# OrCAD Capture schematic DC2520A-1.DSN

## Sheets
1 PAGE1: size Custom; rev: 1
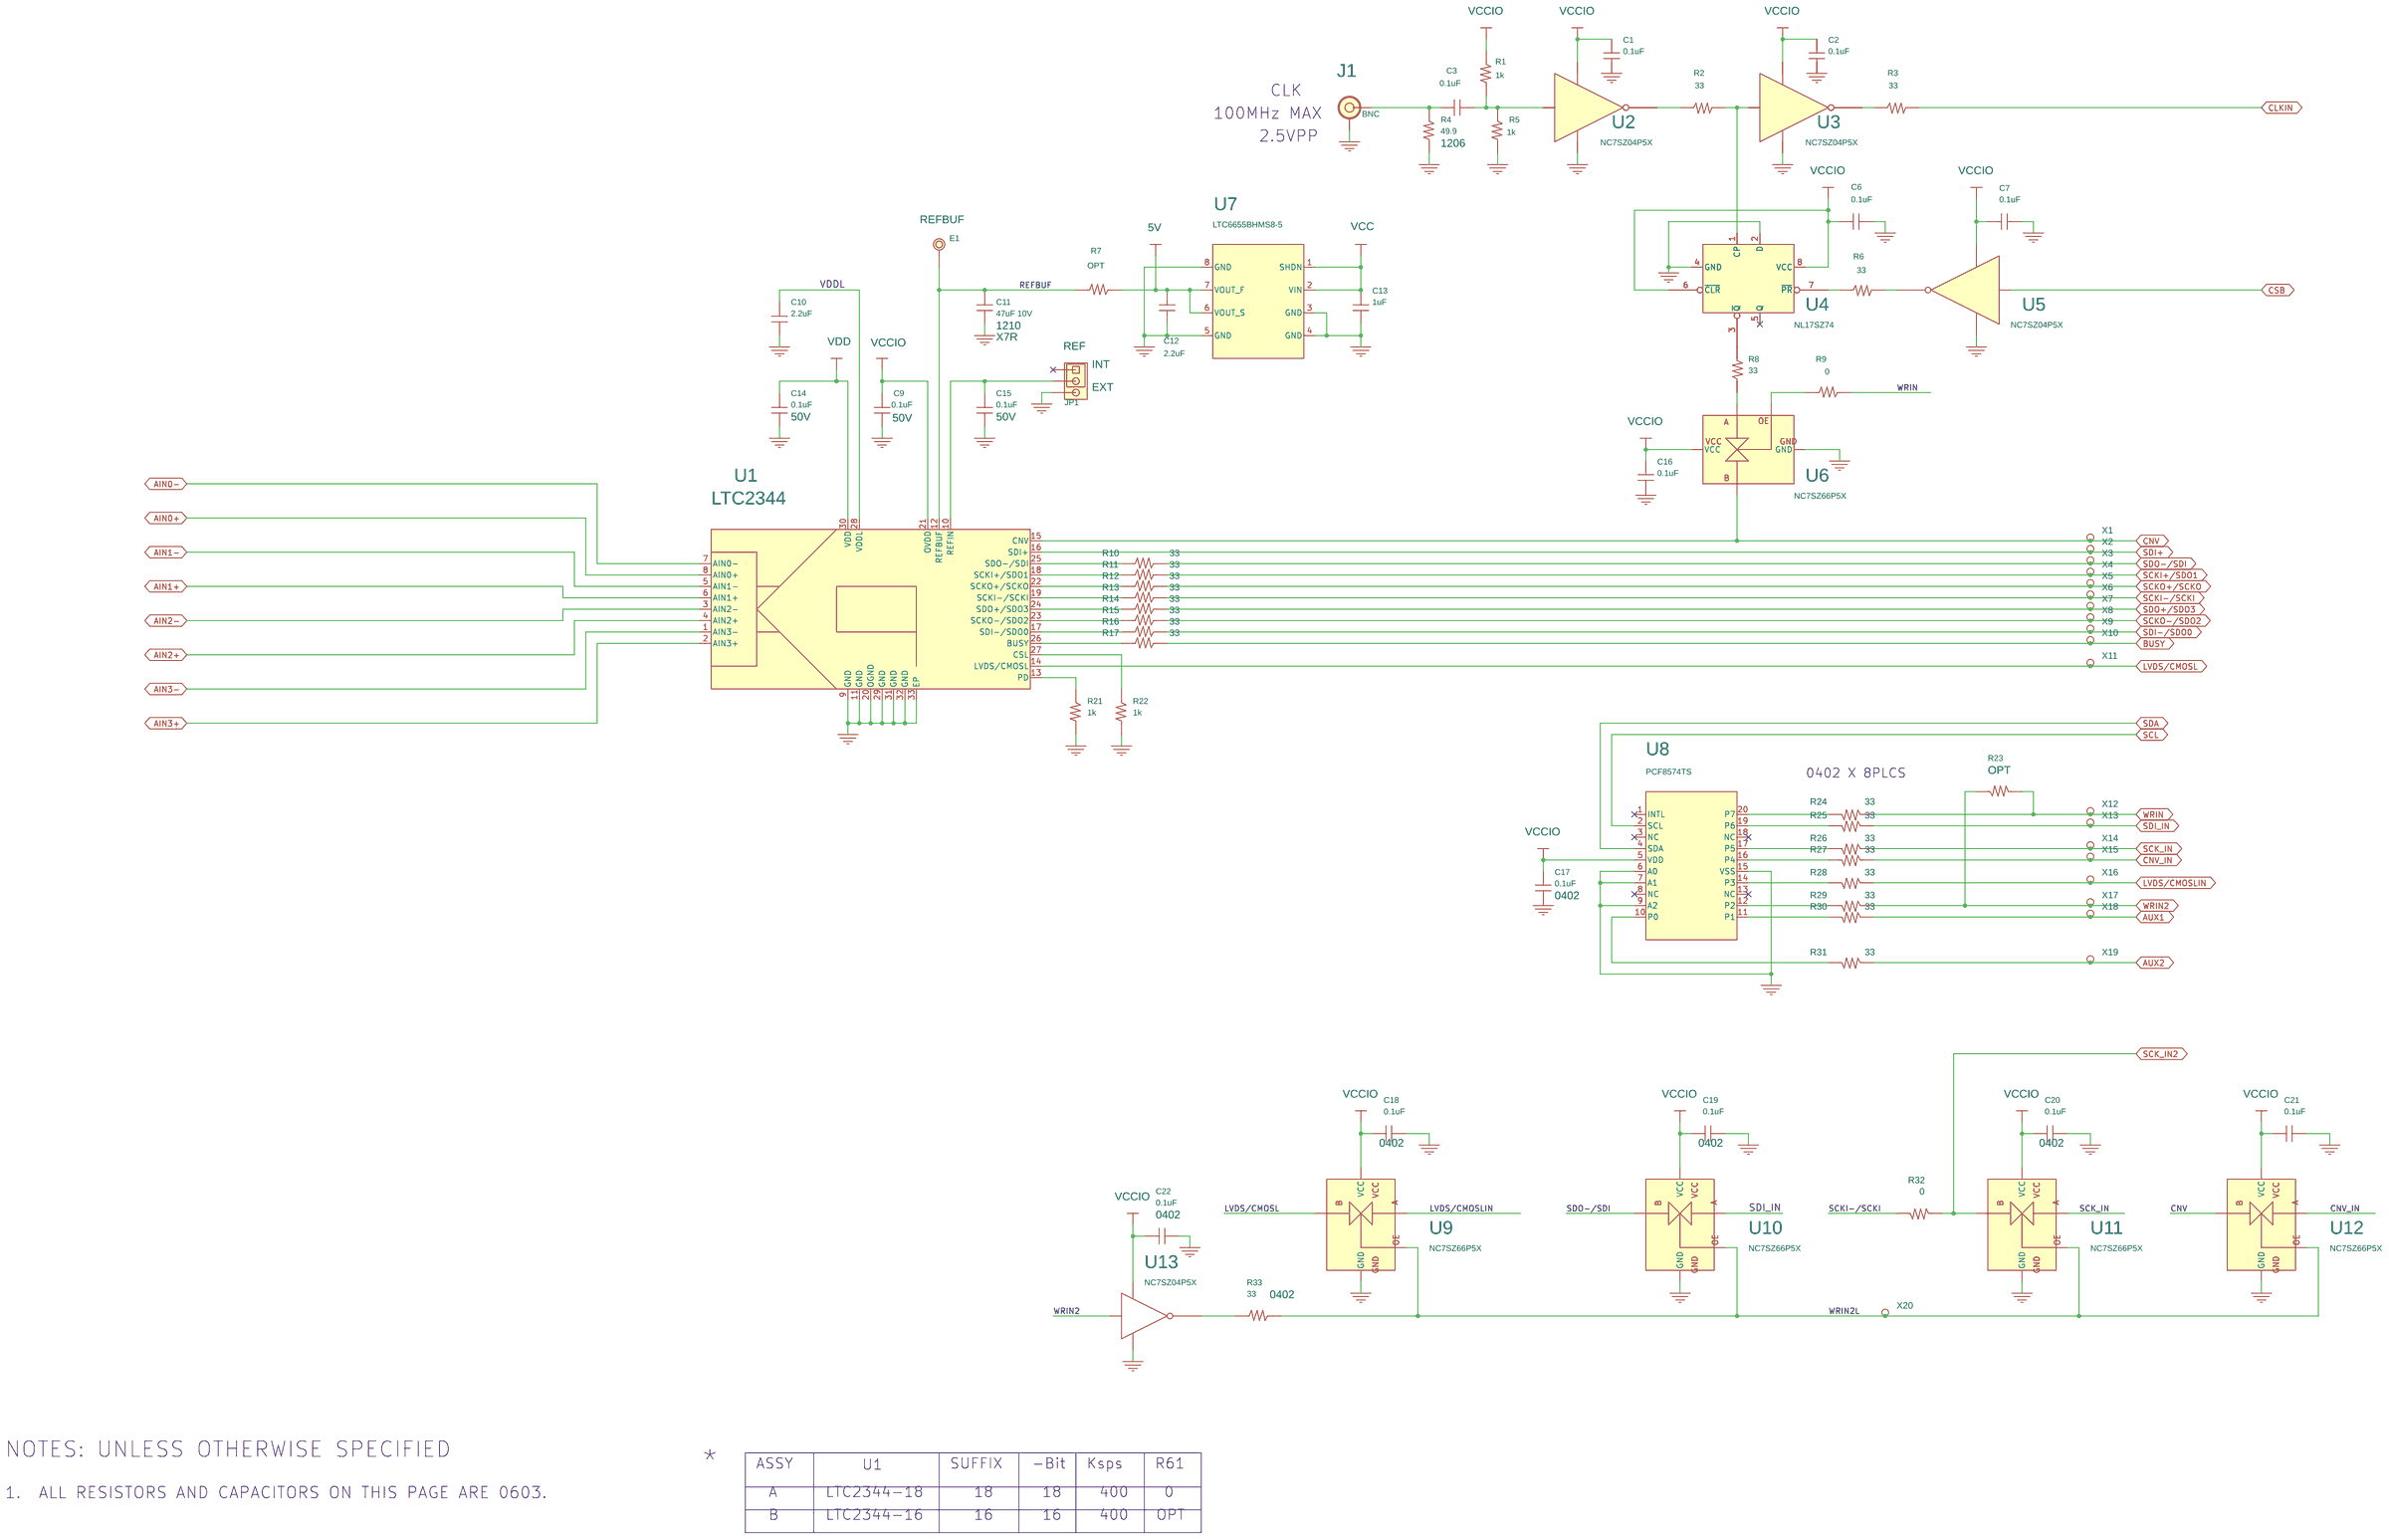
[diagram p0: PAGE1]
2 PAGE2: size B; title: 4-CHANNEL, SOFTSPAN, HIGH SPEED, SERIAL, SAR, ADC; company: LTC2344IUH-18/16; note: DEMO CIRCUIT 2520A; note: B
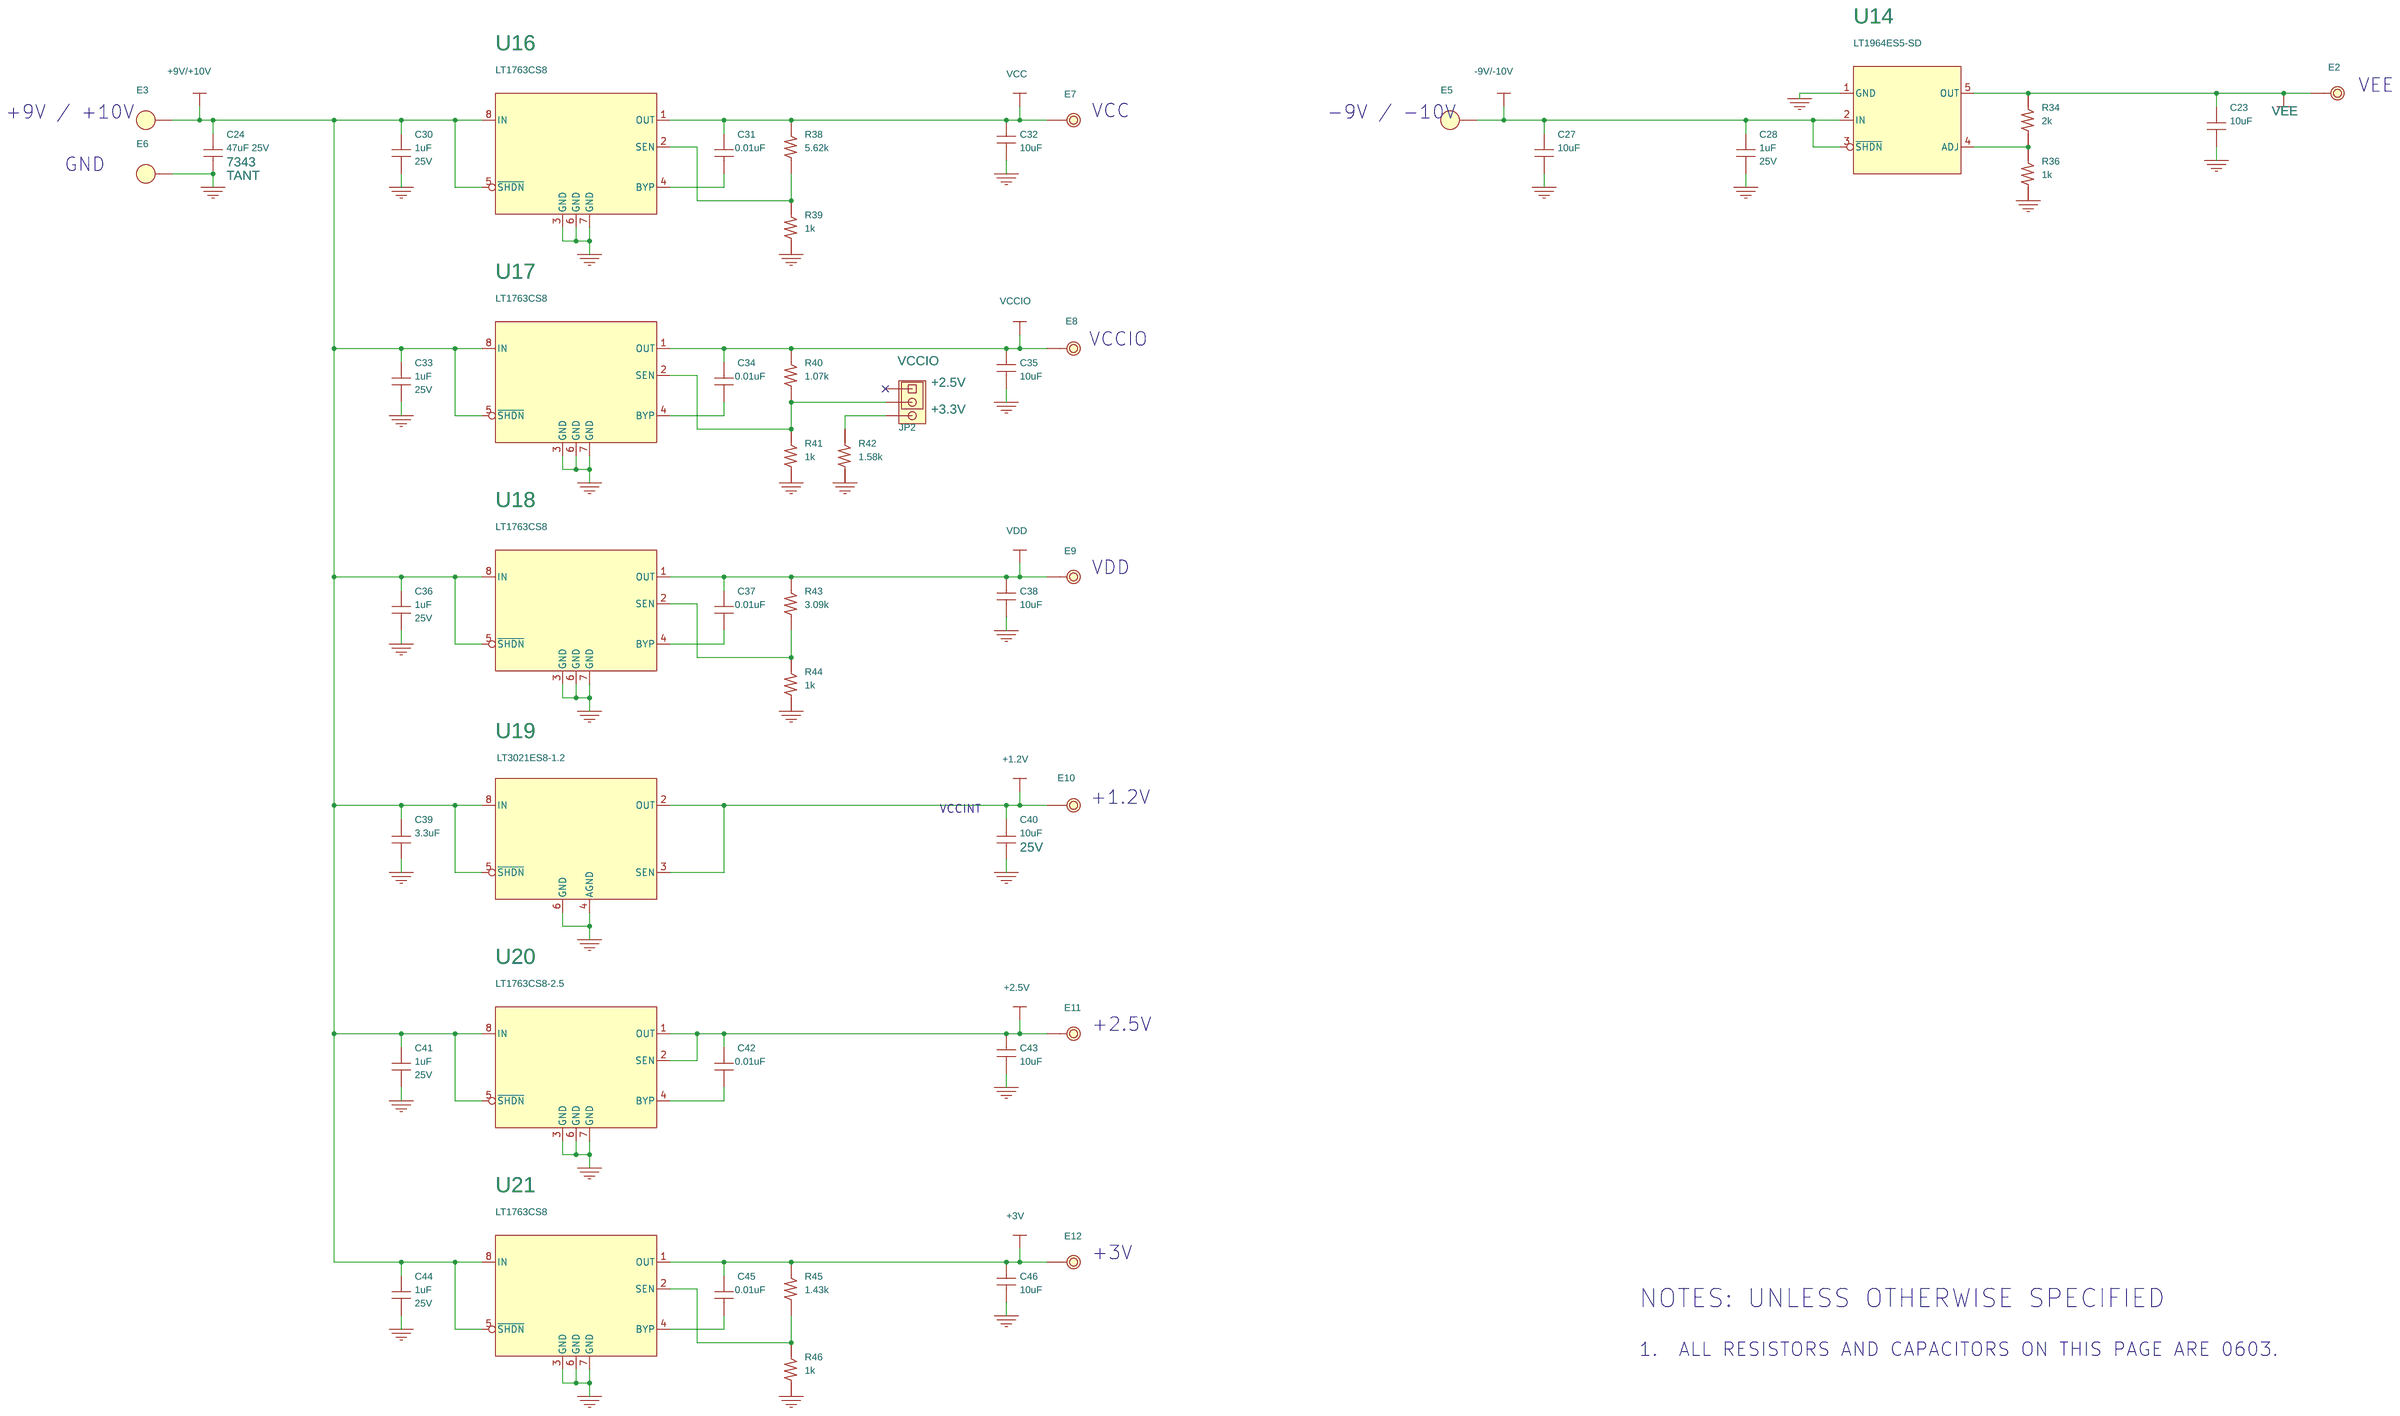
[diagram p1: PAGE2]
3 PAGE3: size B; title: 4-CHANNEL, SOFTSPAN, HIGH SPEED, SERIAL, SAR, ADC; company: LTC2344IUH-18/16; note: DEMO CIRCUIT 2520A; note: B
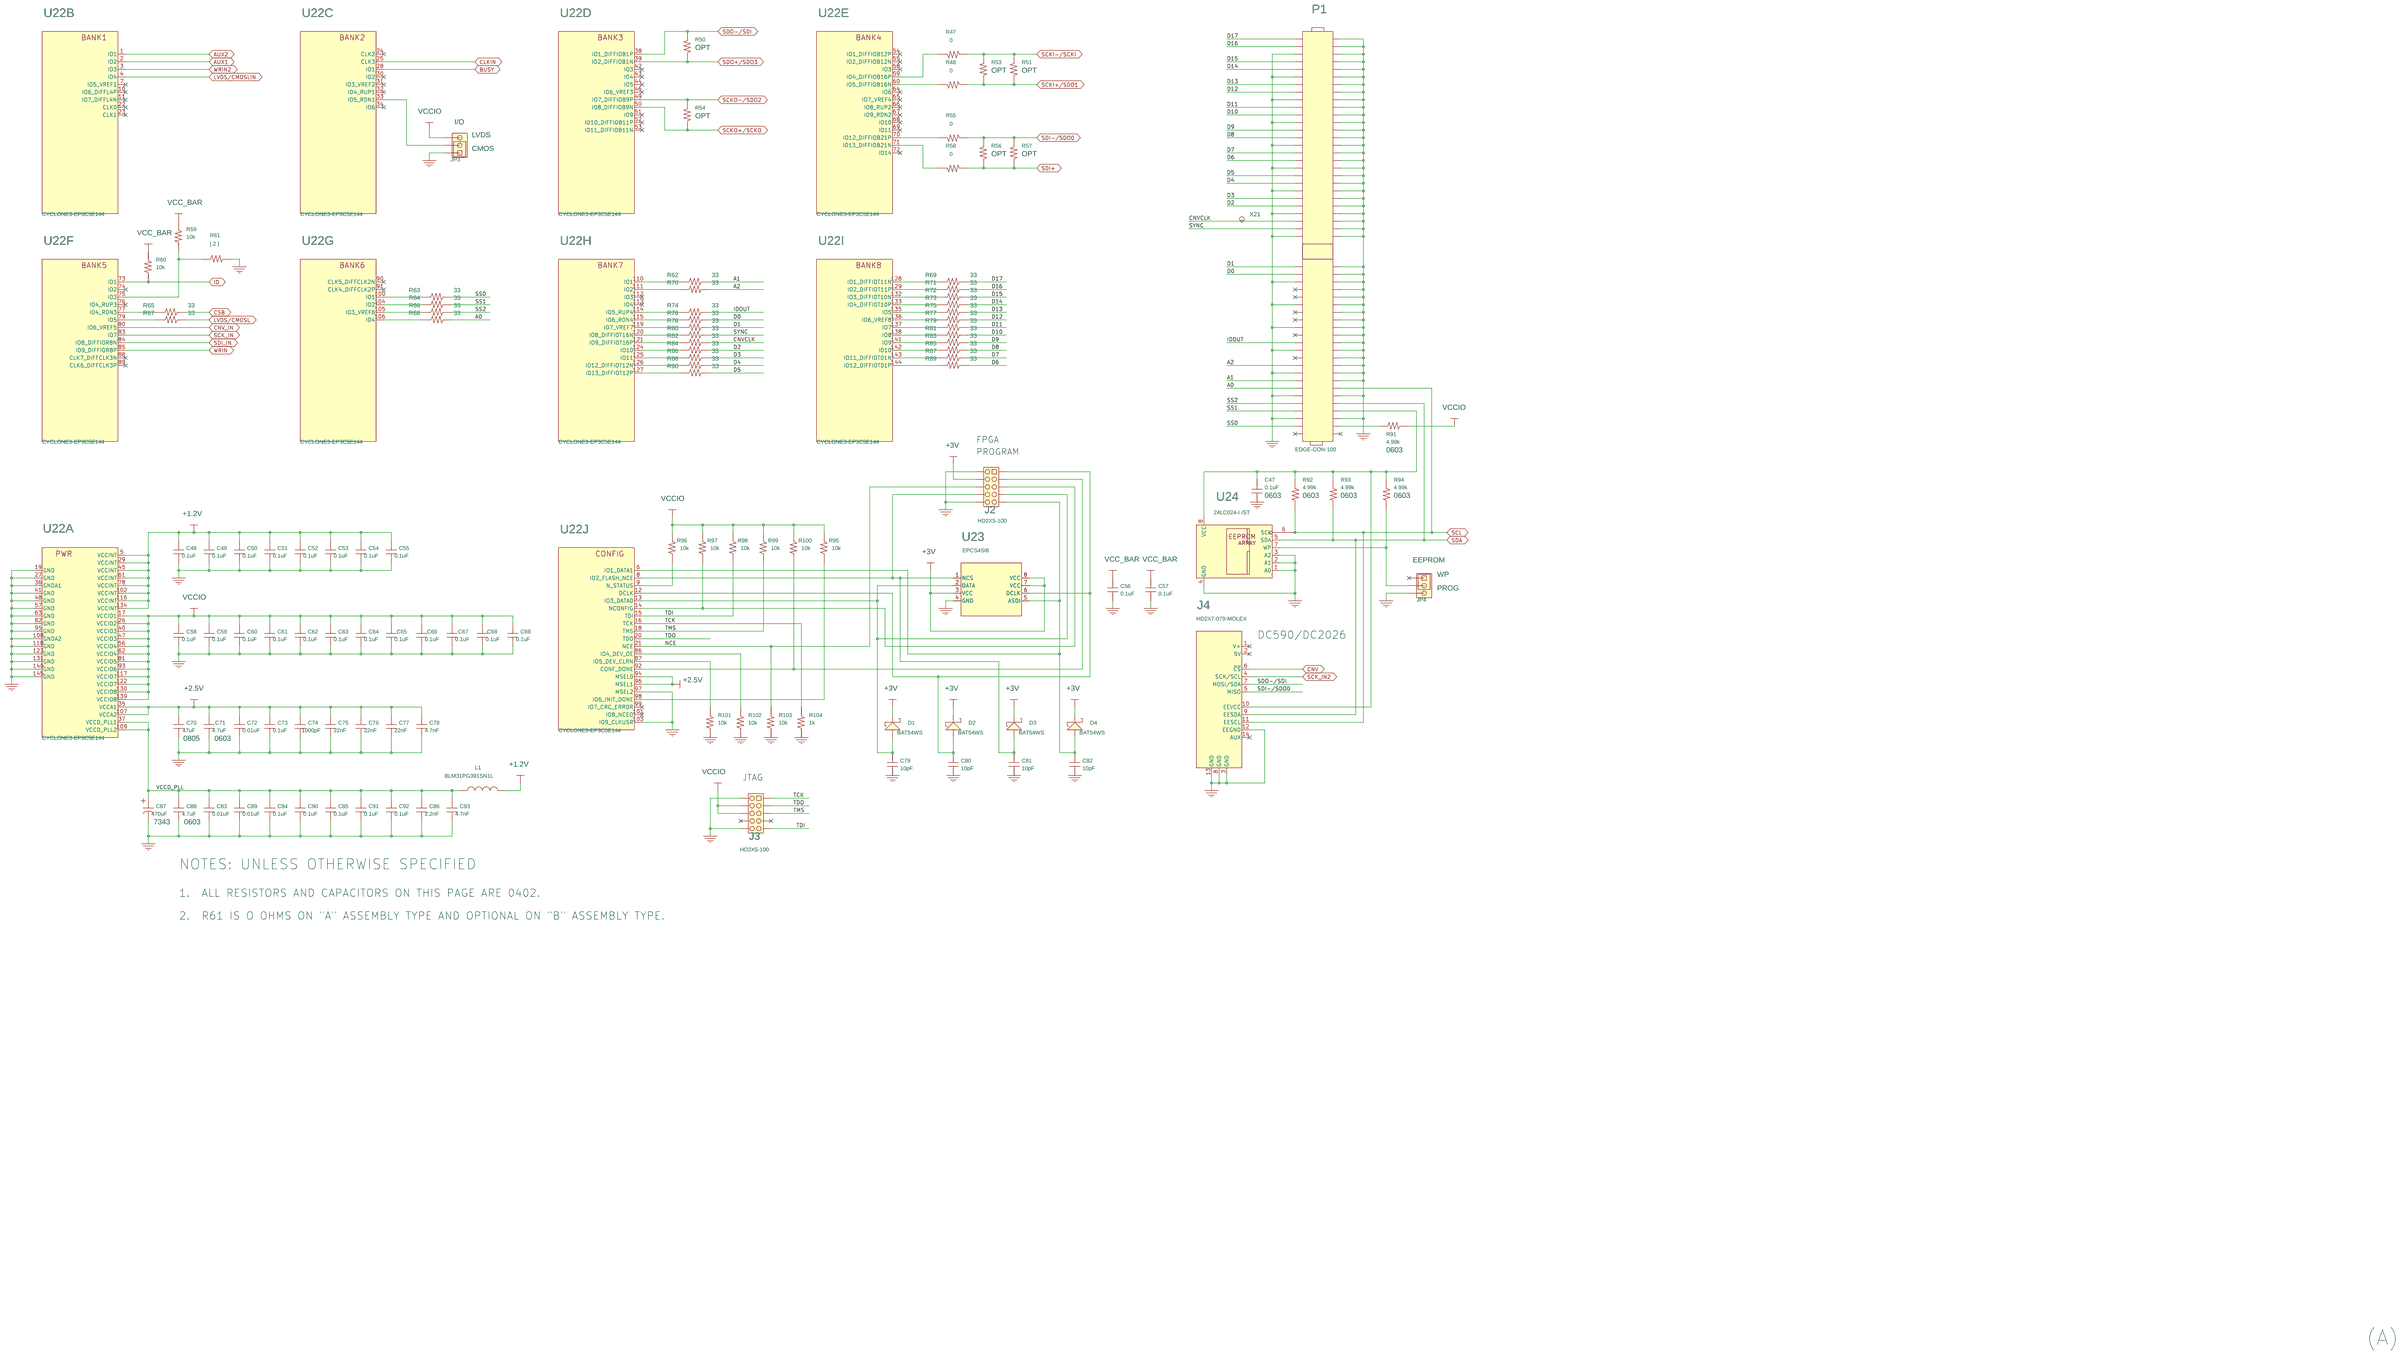
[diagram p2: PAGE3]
4 PAGE4: size C; title: 4-CHANNEL, SOFTSPAN, HIGH SPEED, SERIAL, SAR, ADC; company: LTC2344IUH-18/16; note: DEMO CIRCUIT 2520A; note: B
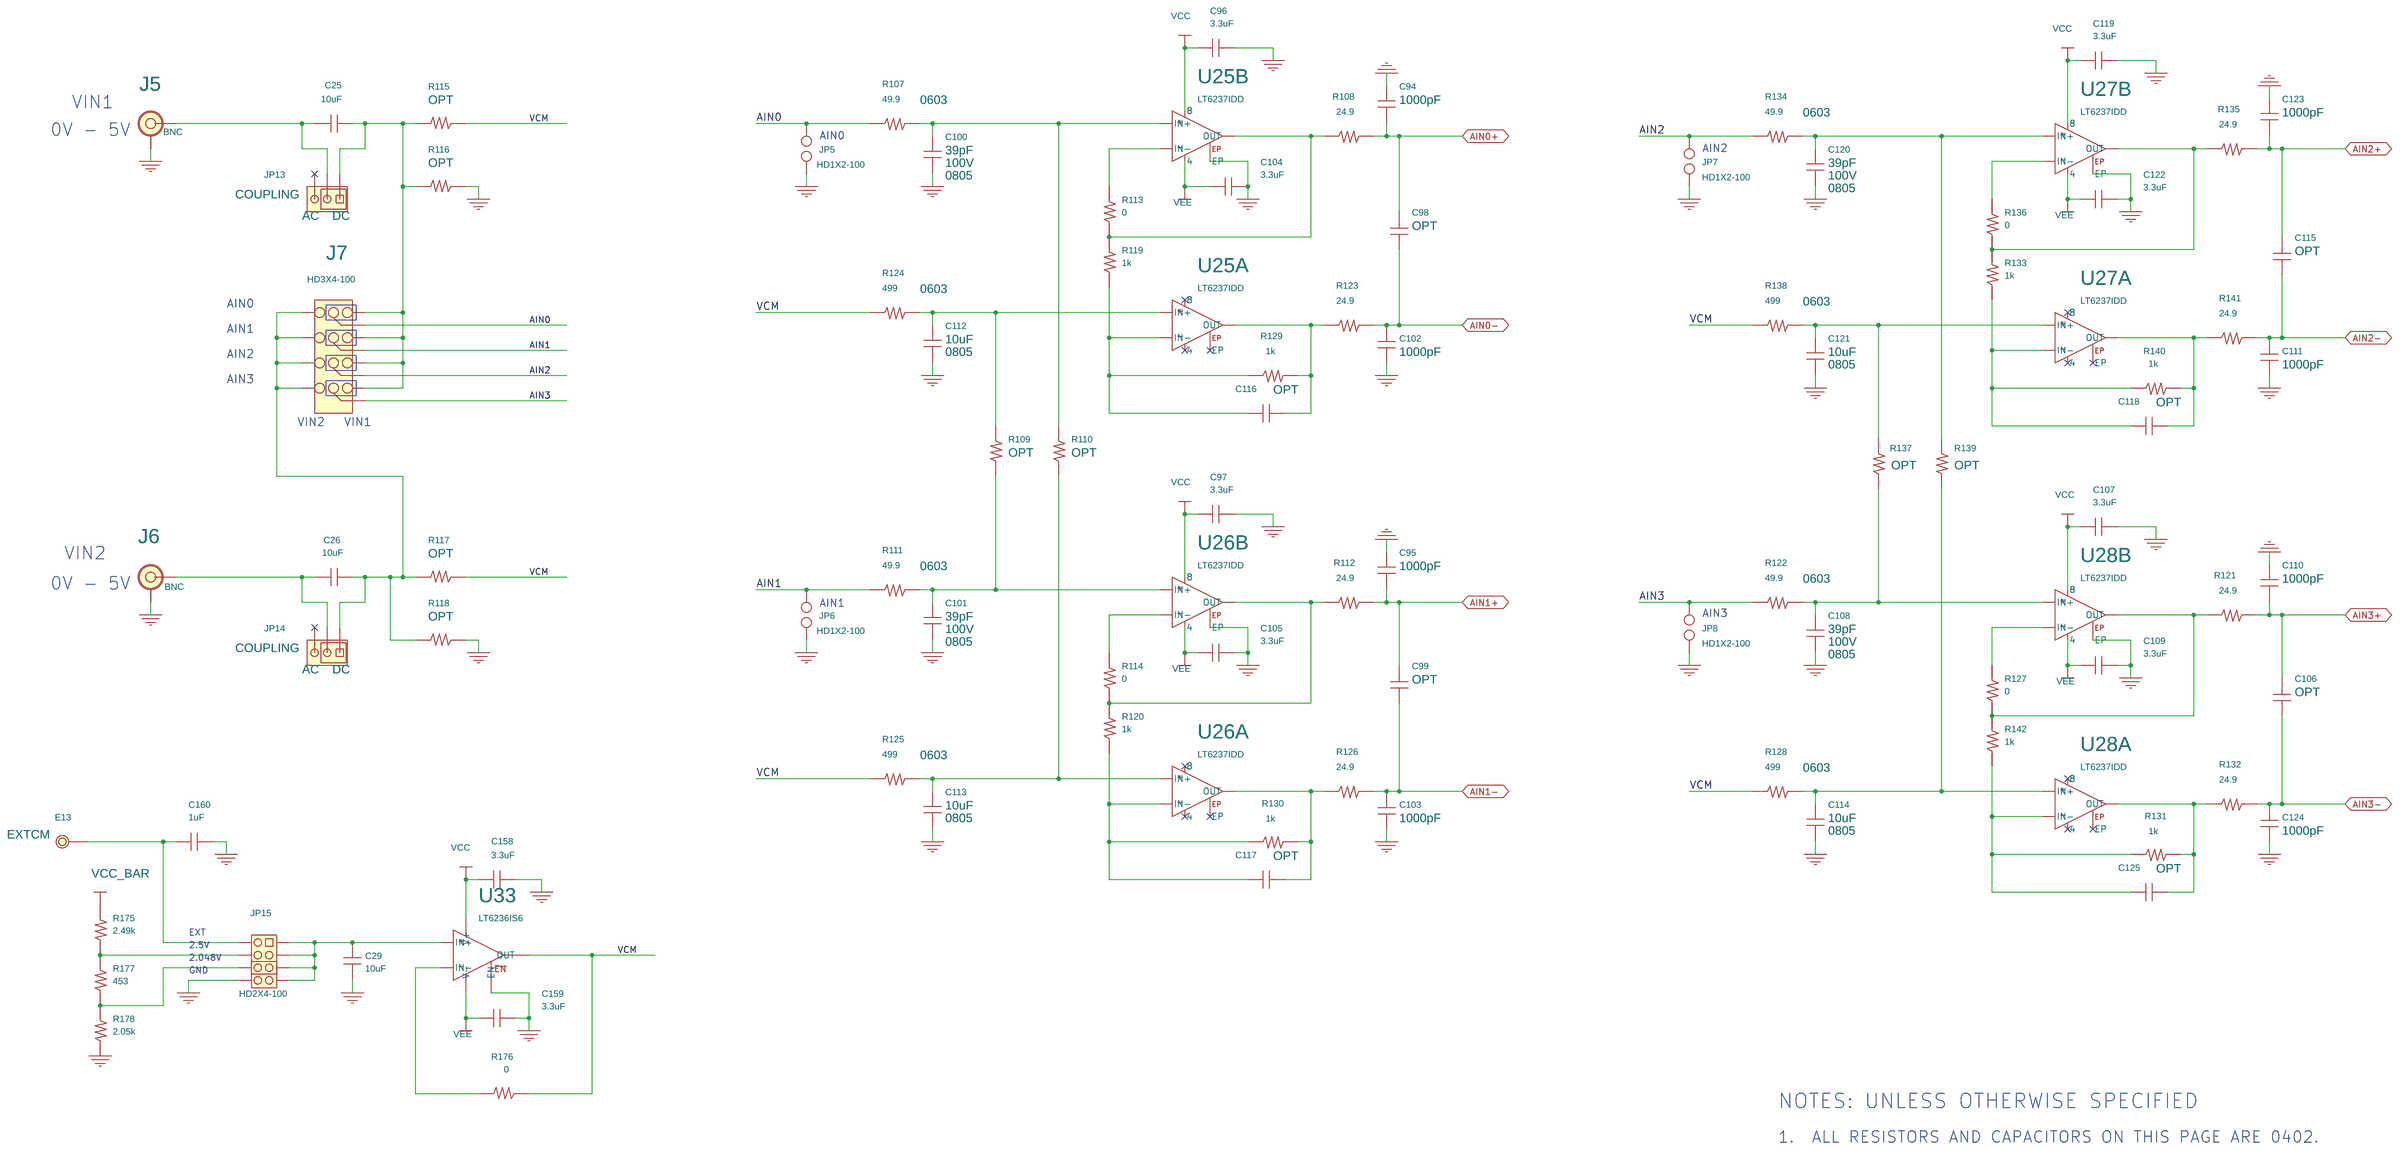
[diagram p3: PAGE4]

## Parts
sheet PAGE1
C1  0.1uF  [0603]
C2  0.1uF  [0603]
C3  0.1uF  [0603]
C6  0.1uF  [0603]
C7  0.1uF  [0603]
C9  0.1uF  [0603]
C10  2.2uF  [0603]
C11  47uF 10V  [1210]
C12  2.2uF  [0603]
C13  1uF  [0603]
C14  0.1uF  [0603]
C15  0.1uF  [0603]
C16  0.1uF  [0603]
C17  0.1uF  [0402]
C18  0.1uF  [0402]
C19  0.1uF  [0402]
C20  0.1uF  [0402]
C21  0.1uF  [0603]
C22  0.1uF  [0402]
E1  MILL-MAX-2308  [MILL-MAX-2308]
J1  BNC  [BNC5]
JP1  HD1X3-100  [HD1X3-100]
R1  1k  [0603]
R2  33  [0603]
R3  33  [0603]
R4  49.9  [1206]
R5  1k  [0603]
R6  33  [0603]
R7  OPT  [0603]
R8  33  [0603]
R9  0  [0603]
R10  33  [0603]
R11  33  [0603]
R12  33  [0603]
R13  33  [0603]
R14  33  [0603]
R15  33  [0603]
R16  33  [0603]
R17  33  [0603]
R21  1k  [0603]
R22  1k  [0603]
R23  R-0402  [0402]
R24  33  [0402]
R25  33  [0402]
R26  33  [0402]
R27  33  [0402]
R28  33  [0402]
R29  33  [0402]
R30  33  [0402]
R31  33  [0402]
R32  0  [0402]
R33  33  [0402]
U1  LTC2344  [QFN32UH-5X5]
U2  NC7SZ04P5X  [SC70-5]
U3  NC7SZ04P5X  [SC70-5]
U4  NL17SZ74  [US8]
U5  NC7SZ04P5X  [SC70-5]
U6  NC7SZ66P5X  [SC70-5]
U7  LTC6655BHMS8-5  [MSOP8]
U8  PCF8574TS  [SSOP20]
U9  NC7SZ66P5X  [SC70-5]
U10  NC7SZ66P5X  [SC70-5]
U11  NC7SZ66P5X  [SC70-5]
U12  NC7SZ66P5X  [SC70-5]
U13  NC7SZ04P5X  [SC70-5]
X1  PAD050-030  [PAD050-030]
X2  PAD050-030  [PAD050-030]
X3  PAD050-030  [PAD050-030]
X4  PAD050-030  [PAD050-030]
X5  PAD050-030  [PAD050-030]
X6  PAD050-030  [PAD050-030]
X7  PAD050-030  [PAD050-030]
X8  PAD050-030  [PAD050-030]
X9  PAD050-030  [PAD050-030]
X10  PAD050-030  [PAD050-030]
X11  PAD050-030  [PAD050-030]
X12  PAD050-030  [PAD050-030]
X13  PAD050-030  [PAD050-030]
X14  PAD050-030  [PAD050-030]
X15  PAD050-030  [PAD050-030]
X16  PAD050-030  [PAD050-030]
X17  PAD050-030  [PAD050-030]
X18  PAD050-030  [PAD050-030]
X19  PAD050-030  [PAD050-030]
X20  PAD050-030  [PAD050-030]
sheet PAGE2
C23  10uF  [0603]
C24  47uF 25V  [7343]
C27  10uF  [0603]
C28  1uF  [0603]
C30  1uF  [0603]
C31  0.01uF  [0603]
C32  10uF  [0603]
C33  1uF  [0603]
C34  0.01uF  [0603]
C35  10uF  [0603]
C36  1uF  [0603]
C37  0.01uF  [0603]
C38  10uF  [0603]
C39  3.3uF  [0603]
C40  10uF  [0603]
C41  1uF  [0603]
C42  0.01uF  [0603]
C43  10uF  [0603]
C44  1uF  [0603]
C45  0.01uF  [0603]
C46  10uF  [0603]
E2  MILL-MAX-2308  [MILL-MAX-2308]
E3  MILL-MAX-2501  [MILL-MAX-2501]
E5  MILL-MAX-2501  [MILL-MAX-2501]
E6  MILL-MAX-2501  [MILL-MAX-2501]
E7  MILL-MAX-2308  [MILL-MAX-2308]
E8  MILL-MAX-2308  [MILL-MAX-2308]
E9  MILL-MAX-2308  [MILL-MAX-2308]
E10  MILL-MAX-2308  [MILL-MAX-2308]
E11  MILL-MAX-2308  [MILL-MAX-2308]
E12  MILL-MAX-2308  [MILL-MAX-2308]
JP2  HD1X3-100  [HD1X3-100]
R34  2k  [0603]
R36  1k  [0603]
R38  5.62k  [0603]
R39  1k  [0603]
R40  1.07k  [0603]
R41  1k  [0603]
R42  1.58k  [0603]
R43  3.09k  [0603]
R44  1k  [0603]
R45  1.43k  [0603]
R46  1k  [0603]
U14  LT1964ES5-SD  [SOT23-S5]
U16  LT1763CS8  [SO8]
U17  LT1763CS8  [SO8]
U18  LT1763CS8  [SO8]
U19  LT3021ES8-1.2  [SO8]
U20  LT1763CS8-2.5  [SO8]
U21  LT1763CS8  [SO8]
sheet PAGE3
C47  0.1uF  [0603]
C48  0.1uF  [0402]
C49  0.1uF  [0402]
C50  0.1uF  [0402]
C51  0.1uF  [0402]
C52  0.1uF  [0402]
C53  0.1uF  [0402]
C54  0.1uF  [0402]
C55  0.1uF  [0402]
C56  0.1uF  [0402]
C57  0.1uF  [0402]
C58  0.1uF  [0402]
C59  0.1uF  [0402]
C60  0.1uF  [0402]
C61  0.1uF  [0402]
C62  0.1uF  [0402]
C63  0.1uF  [0402]
C64  0.1uF  [0402]
C65  0.1uF  [0402]
C66  0.1uF  [0402]
C67  0.1uF  [0402]
C68  0.1uF  [0402]
C69  0.1uF  [0402]
C70  47uF  [0805]
C71  4.7uF  [0603]
C72  0.01uF  [0402]
C73  0.1uF  [0402]
C74  1000pF  [0402]
C75  22nF  [0402]
C76  22nF  [0402]
C77  22nF  [0402]
C78  4.7nF  [0402]
C79  10pF  [0402]
C80  10pF  [0402]
C81  10pF  [0402]
C82  10pF  [0402]
C83  0.01uF  [0402]
C84  0.1uF  [0402]
C85  0.1uF  [0402]
C86  2.2nF  [0402]
C87  470uF  [7343]
C88  4.7uF  [0603]
C89  0.01uF  [0402]
C90  0.1uF  [0402]
C91  0.1uF  [0402]
C92  0.1uF  [0402]
C93  4.7nF  [0402]
D1  BAT54WS  [SOD323]
D2  BAT54WS  [SOD323]
D3  BAT54WS  [SOD323]
D4  BAT54WS  [SOD323]
J2  HD2X5-100  [HD2X5-100]
J3  HD2X5-100  [HD2X5-100]
J4  HD2X7-079-MOLEX  [HD2X7-079-MOLEX]
JP3  HD1X3-100  [HD1X3-100]
JP4  HD1X3-100  [HD1X3-100]
L1  BLM31PG391SN1L  [1206]
P1  EDGE-CON-100  [CON-GOLD-100P-TB]
R47  0  [0402]
R48  0  [0402]
R50  R-0402  [0402]
R51  R-0402  [0402]
R53  R-0402  [0402]
R54  R-0402  [0402]
R55  0  [0402]
R56  R-0402  [0402]
R57  R-0402  [0402]
R58  0  [0402]
R59  10k  [0402]
R60  10k  [0402]
R61  [ 2 ]  [0402]
R62  33  [0402]
R63  33  [0402]
R64  33  [0402]
R65  33  [0402]
R66  33  [0402]
R67  33  [0402]
R68  33  [0402]
R69  33  [0402]
R70  33  [0402]
R71  33  [0402]
R72  33  [0402]
R73  33  [0402]
R74  33  [0402]
R75  33  [0402]
R76  33  [0402]
R77  33  [0402]
R78  33  [0402]
R79  33  [0402]
R80  33  [0402]
R81  33  [0402]
R82  33  [0402]
R83  33  [0402]
R84  33  [0402]
R85  33  [0402]
R86  33  [0402]
R87  33  [0402]
R88  33  [0402]
R89  33  [0402]
R90  33  [0402]
R91  4.99k  [0603]
R92  4.99k  [0603]
R93  4.99k  [0603]
R94  4.99k  [0603]
R95  10k  [0402]
R96  10k  [0402]
R97  10k  [0402]
R98  10k  [0402]
R99  10k  [0402]
R100  10k  [0402]
R101  10k  [0402]
R102  10k  [0402]
R103  10k  [0402]
R104  1k  [0402]
U22  CYCLONE3-EP3C5E144  [EQFP144]  (sections A,B,C,D,E,F,G,H,I,J)
U23  EPCS4SI8  [SO8]
U24  24LC024-I /ST  [TSSOP8]
X21  PAD050-030  [PAD050-030]
sheet PAGE4
C25  10uF  [0603]
C26  10uF  [0603]
C29  10uF  [0603]
C94  1000pF  [0402]
C95  1000pF  [0402]
C96  3.3uF  [0402]
C97  3.3uF  [0402]
C98  C-0402  [0402]
C99  C-0402  [0402]
C100  39pF  [0805]
C101  39pF  [0805]
C102  1000pF  [0402]
C103  1000pF  [0402]
C104  3.3uF  [0402]
C105  3.3uF  [0402]
C106  C-0402  [0402]
C107  3.3uF  [0402]
C108  39pF  [0805]
C109  3.3uF  [0402]
C110  1000pF  [0402]
C111  1000pF  [0402]
C112  10uF  [0805]
C113  10uF  [0805]
C114  10uF  [0805]
C115  C-0402  [0402]
C116  C-0402  [0402]
C117  C-0402  [0402]
C118  C-0402  [0402]
C119  3.3uF  [0402]
C120  39pF  [0805]
C121  10uF  [0805]
C122  3.3uF  [0402]
C123  1000pF  [0402]
C124  1000pF  [0402]
C125  C-0402  [0402]
C158  3.3uF  [0402]
C159  3.3uF  [0402]
C160  1uF  [0402]
E13  MILL-MAX-2308  [MILL-MAX-2308]
J5  BNC  [BNC5]
J6  BNC  [BNC5]
J7  HD3X4-100  [HD3X4-100]
JP5  HD1X2-100  [HD1X2-100]
JP6  HD1X2-100  [HD1X2-100]
JP7  HD1X2-100  [HD1X2-100]
JP8  HD1X2-100  [HD1X2-100]
JP13  HD1X3-100  [HD1X3-100]
JP14  HD1X3-100  [HD1X3-100]
JP15  HD2X4-100  [HD2X4-100]
R107  49.9  [0603]
R108  24.9  [0402]
R109  R-0402  [0402]
R110  R-0402  [0402]
R111  49.9  [0603]
R112  24.9  [0402]
R113  0  [0402]
R114  0  [0402]
R115  R-0402  [0402]
R116  R-0402  [0402]
R117  R-0402  [0402]
R118  R-0402  [0402]
R119  1k  [0402]
R120  1k  [0402]
R121  24.9  [0402]
R122  49.9  [0603]
R123  24.9  [0402]
R124  499  [0603]
R125  499  [0603]
R126  24.9  [0402]
R127  0  [0402]
R128  499  [0603]
R129  1k  [0402]
R130  1k  [0402]
R131  1k  [0402]
R132  24.9  [0402]
R133  1k  [0402]
R134  49.9  [0603]
R135  24.9  [0402]
R136  0  [0402]
R137  R-0402  [0402]
R138  499  [0603]
R139  R-0402  [0402]
R140  1k  [0402]
R141  24.9  [0402]
R142  1k  [0402]
R175  2.49k  [0402]
R176  0  [0402]
R177  453  [0402]
R178  2.05k  [0402]
U25  LT6237IDD  [DFN8DD-3X3]  (sections A,B)
U26  LT6237IDD  [DFN8DD-3X3]  (sections A,B)
U27  LT6237IDD  [DFN8DD-3X3]  (sections A,B)
U28  LT6237IDD  [DFN8DD-3X3]  (sections A,B)
U33  LT6236IS6  [TSOT23-6]

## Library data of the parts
C1-C3 C6 C7 C10 C12 C13 C16-C22 C25 C26 C29 C31 C32 C34 C37 C39 C42 C45 C47-C86 C88-C97 C102-C105 C107 C109-C114 C119 C121-C124 C158-C160 = CAP-NP
C9 C14 C15 = CAP-NP: 1st Part Field: 50V
C11 = CAP-NP: 1st Part Field: X7R
E1 = E-064: 1st Part Field: REFBUF
J1 = BNC: 1st Part Field: <1st Part Field>
JP1 = HD1X3: 1st Part Field: REF; 2nd Part Field: EXT; 3rd Part Field: INT
R1-R17 R21 R22 R24-R34 R36 R38-R48 R55 R58-R104 R107 R108 R111-R114 R119-R136 R138 R140-R142 R175-R178 = R
R23 R50 R51 R53 R54 R56 R57 R109 R110 R115-R118 R137 R139 = R: OPT: OPT
U1 = LTC2344IUH-QFN32UH-5X5
U2 U3 U5 = NC7SZ04P5X-ONE
U4 = NL17SZ74-US8
U6 U9-U12 = NC7SZ66P5X-SC70-5
U7 = LTC6655AHMSH-5
U8 = PCF8574TS-SSOP20
U13 = NC7SZ04P5X-SC70-5
X1-X21 = E-HOLE
C23 C27 C28 C30 C33 C35 C36 C38 C41 C43 C44 C46 = CAP-NP: 1ST PART FIELD: 25V
C24 = CAP-NP: 1ST PART FIELD: 16V; 2nd Part Field: TANT; 5TH PART FIELD: 1210
C40 = CAP-NP: 1st Part Field: 25V
E2 E7-E12 = E-064
E3 E5 E6 = E-094
JP2 = HD1X3: 1st Part Field: VCCIO; 2nd Part Field: +3.3V; 3rd Part Field: +2.5V
U14 = LT1964ES5-SD-SOT23-5
U16-U18 U20 U21 = LT1763CS8-SO8
U19 = LT3021ES8-SO8
C87 = CAP
D1-D4 = BAT54WS-SOD323
J2 J3 = HD2X5-100_0
J4 = HD2X7-079-MOLEX
JP3 = HD1X3: 1st Part Field: I/O; 2nd Part Field: LVDS; 3rd Part Field: CMOS
JP4 = HD1X3: 1st Part Field: EEPROM; 2nd Part Field: PROG; 3rd Part Field: WP
L1 = IND
P1 = CON-EDGE-100P-TB
U22 = CYCLONE3-EP3C5E144-EQFP144
U23 = EPCS4SI8-SO8
U24 = 24LC025-I_ST
C98 C99 C106 C115-C118 C125 = CAP-NP: OPT: OPT
C100 C101 C108 C120 = CAP-NP: VOLTAGE: 100V
E13 = E-064: PART FIELD 1: EXTCM
J5 J6 = BNC
J7 = HD3X4-100
JP5-JP8 = HD1X2-100
JP13 JP14 = HD1X3: 1st Part Field: COUPLING; 2nd Part Field: AC; 3rd Part Field: DC
JP15 = HD2X4-100_1
U25 = LT6237IDD-DFN8DD-3X3_4
U26 = LT6237IDD-DFN8DD-3X3_6
U27 = LT6237IDD-DFN8DD-3X3_5
U28 = LT6237IDD-DFN8DD-3X3_1
U33 = LT6236CS6-TSOT23-6

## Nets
5V: C12.2 R7.1 R175.2 U7.6(VOUT_S) U7.7(VOUT_F)
+1.2V: C40.2 C48.2 C49.2 C50.2 C51.2 C52.2 C53.2 C54.2 C55.2 E10.1(A) L1.2 U19.2(OUT) U19.3(SEN) U22.5(VCCINT) U22.29(VCCINT) U22.45(VCCINT) U22.61(VCCINT) U22.78(VCCINT) U22.102(VCCINT) U22.116(VCCINT) U22.134(VCCINT)
+2.5V: C42.1 C43.1 C70.2 C71.2 C72.2 C73.2 C74.2 C75.2 C76.2 C77.2 C78.2 E11.1(A) U20.1(OUT) U20.2(SEN) U22.35(VCCA1) U22.94(MSEL0) U22.96(MSEL1) U22.107(VCCA2)
+3V: C45.1 C46.1 C56.2 C57.2 D1.1 D2.1 D3.1 D4.1 E12.1(A) J2.4 R45.1 U21.1(OUT) U23.3(VCC) U23.7(VCC) U23.8(VCC)
+9V/+10V: C24.1 C30.1 C33.1 C36.1 C39.2 C41.1 C44.1 E3.1(A) U16.5(~{SHDN}) U16.8(IN) U17.5(~{SHDN}) U17.8(IN) U18.5(~{SHDN}) U18.8(IN) U19.5(~{SHDN}) U19.8(IN) U20.5(~{SHDN}) U20.8(IN) U21.5(~{SHDN}) U21.8(IN)
-9V/-10V: C27.1 C28.1 E5.1(A) U14.2(IN) U14.3(~{SHDN})
GND: C1.2 C2.2 C6.2 C7.2 C9.1 C10.1 C11.1 C12.1 C13.1 C14.1 C15.1 C16.2 C17.2 C18.2 C19.2 C20.2 C21.2 C22.1 C23.2 C24.2 C27.2 C28.2 C29.2 C30.2 C32.2 C33.2 C35.2 C36.2 C38.2 C39.1 C40.1 C41.2 C43.2 C44.2 C46.2 C47.1 C48.1 C49.1 C50.1 C51.1 C52.1 C53.1 C54.1 C55.1 C56.1 C57.1 C58.1 C59.1 C60.1 C61.1 C62.1 C63.1 C64.1 C65.1 C66.1 C67.1 C68.1 C69.1 C70.1 C71.1 C72.1 C73.1 C74.1 C75.1 C76.1 C77.1 C78.1 C79.1 C80.1 C81.1 C82.1 C83.1 C84.1 C85.1 C86.1 C87.2 C88.1 C89.1 C90.1 C91.1 C92.1 C93.1 C94.1 C95.1 C96.2 C97.2 C100.2 C101.2 C102.1 C103.1 C104.2 C105.2 C107.2 C108.2 C109.2 C110.1 C111.1 C112.2 C113.2 C114.2 C119.2 C120.2 C121.2 C122.2 C123.1 C124.1 C158.2 C159.2 C160.2 E6.1(A) J1.2 J1.3 J1.4 J1.5 J2.2 J2.10 J3.2 J3.10 J4.3(GND) J4.8(GND) J4.12(EEGND) J4.13(GND) J5.2 J5.3 J5.4 J5.5 J6.2 J6.3 J6.4 J6.5 JP1.3 JP3.1 JP4.3 JP5.2 JP6.2 JP7.2 JP8.2 JP15.8 P1.1 P1.3 P1.5 P1.6 P1.7 P1.9 P1.11 P1.12 P1.13 P1.15 P1.17 P1.18 P1.19 P1.21 P1.23 P1.24 P1.25 P1.27 P1.29 P1.30 P1.31 P1.33 P1.35 P1.36 P1.37 P1.39 P1.41 P1.42 P1.43 P1.45 P1.47 P1.48 P1.49 P1.51 P1.53 P1.54 P1.55 P1.57 P1.59 P1.60 P1.61 P1.63 P1.65 P1.66 P1.67 P1.69 P1.71 P1.72 P1.73 P1.75 P1.77 P1.78 P1.79 P1.81 P1.83 P1.84 P1.85 P1.89 P1.90 P1.95 P1.96 R4.2 R5.2 R21.2 R22.2 R36.2 R39.2 R41.2 R42.2 R44.2 R46.2 R61.1 R101.2 R102.2 R103.2 R104.2 R116.1 R118.1 R178.1 U1.9(GND) U1.11(GND) U1.20(OGND) U1.29(GND) U1.31(GND) U1.32(GND) U1.33(EP) U2.3 U3.3 U4.2(D) U4.4(GND) U5.3 U6.3(GND) U7.3(GND) U7.4(GND) U7.5(GND) U7.8(GND) U8.6(A0) U8.7(A1) U8.9(A2) U8.15(VSS) U9.3(GND) U10.3(GND) U11.3(GND) U12.3(GND) U13.3 U14.1(GND) U16.3(GND) U16.6(GND) U16.7(GND) U17.3(GND) U17.6(GND) U17.7(GND) U18.3(GND) U18.6(GND) U18.7(GND) U19.4(AGND) U19.6(GND) U20.3(GND) U20.6(GND) U20.7(GND) U21.3(GND) U21.6(GND) U21.7(GND) U22.19(GND) U22.27(GND) U22.36(GNDA1) U22.41(GND) U22.48(GND) U22.57(GND) U22.63(GND) U22.82(GND) U22.95(GND) U22.97(MSEL2) U22.103(IO9_CLKUSR) U22.108(GNDA2) U22.118(GND) U22.123(GND) U22.131(GND) U22.140(GND) U22.145(GND) U23.4(GND) U24.1(A0) U24.2(A1) U24.3(A2) U24.4(GND) U25.9(EP) U26.9(EP) U27.9(EP) U28.9(EP) U33.5(EN)
VCC: C13.2 C31.1 C32.1 C96.1 C97.1 C107.1 C119.1 C158.1 E7.1(A) R38.1 U7.1(SHDN) U7.2(VIN) U16.1(OUT) U25.8 U26.8 U27.8 U28.8 U33.6(V+)
VCCD_PLL: C83.2 C84.2 C85.2 C86.2 C87.1 C88.2 C89.2 C90.2 C91.2 C92.2 C93.2 L1.1 U22.37(VCCD_PLL1) U22.109(VCCD_PLL2)
VCCIO: C1.1 C2.1 C6.1 C7.1 C9.2 C16.1 C17.1 C18.1 C19.1 C20.1 C21.1 C22.2 C34.1 C35.1 C58.2 C59.2 C60.2 C61.2 C62.2 C63.2 C64.2 C65.2 C66.2 C67.2 C68.2 C69.2 E8.1(A) J3.4 J3.6 JP3.3 R1.1 R40.1 R59.1 R60.1 R91.1 R95.1 R96.1 R97.1 R98.1 R99.1 R100.1 U1.21(OVDD) U2.5 U3.5 U4.6(~{CLR}) U4.8(VCC) U5.5 U6.5(VCC) U8.5(VDD) U9.5(VCC) U10.5(VCC) U11.5(VCC) U12.5(VCC) U13.5 U17.1(OUT) U22.17(VCCIO1) U22.26(VCCIO2) U22.40(VCCIO3) U22.47(VCCIO3) U22.56(VCCIO4) U22.62(VCCIO4) U22.81(VCCIO5) U22.93(VCCIO6) U22.117(VCCIO7) U22.122(VCCIO7) U22.130(VCCIO8) U22.139(VCCIO8)
VDD: C14.2 C37.1 C38.1 E9.1(A) R43.1 U1.30(VDD) U18.1(OUT)
VDDL: C10.2 U1.28(VDDL)
VEE: C23.1 C104.1 C105.1 C109.1 C122.1 C159.1 E2.1(A) R34.1 U14.5(OUT) U25.4 U26.4 U27.4 U28.4 U33.2(V-)
A0: P1.88 R68.1
A1: P1.86 R62.1
A2: P1.82 R70.1
AIN0: J7.5 JP5.1 R107.1
AIN0+: C94.2 C98.2 R108.2 U1.8(AIN0+)
AIN0-: C98.1 C102.2 R123.2 U1.7(AIN0-)
AIN1: J7.6 JP6.1 R111.1
AIN1+: C95.2 C99.2 R112.2 U1.6(AIN1+)
AIN1-: C99.1 C103.2 R126.2 U1.5(AIN1-)
AIN2: J7.7 JP7.1 R134.1
AIN2+: C115.2 C123.2 R135.2 U1.4(AIN2+)
AIN2-: C111.2 C115.1 R141.2 U1.3(AIN2-)
AIN3: J7.8 JP8.1 R122.1
AIN3+: C106.2 C110.2 R121.2 U1.2(AIN3+)
AIN3-: C106.1 C124.2 R132.2 U1.1(AIN3-)
AUX1: R30.1 U22.2(IO2) X18.1
AUX2: R31.1 U22.1(IO1) X19.1
BUSY: R17.1 U22.28(IO1) X10.1
CLKIN: R3.2 U22.25(CLK3)
CNV: J4.6(~{CS}) U1.15(CNV) U6.2 U12.2 X1.1
CNV_IN: R27.1 U12.1 U22.80(IO6_VREF5) X15.1
CNVCLK: P1.50 R82.1 X21.1
CSB: R65.1 U5.2
D0: P1.58 R76.1
D1: P1.56 R78.1
D2: P1.46 R84.1
D3: P1.44 R86.1
D4: P1.40 R88.1
D5: P1.38 R90.1
D6: P1.34 R89.1
D7: P1.32 R87.1
D8: P1.28 R85.1
D9: P1.26 R83.1
D10: P1.22 R81.1
D11: P1.20 R79.1
D12: P1.16 R77.1
D13: P1.14 R75.1
D14: P1.10 R73.1
D15: P1.8 R72.1
D16: P1.4 R71.1
D17: P1.2 R69.1
ID: R60.2 U22.73(IO1)
IDOUT: P1.76 R74.1
LVDS/CMOSL: R67.1 U1.14(LVDS/CMOSL) U9.2 X11.1
LVDS/CMOSLIN: R28.1 U9.1 U22.4(IO4) X16.1
NCE: J2.6 R103.1 U22.21(NCE)
REFBUF: C11.2 E1.1(A) R7.2 U1.12(REFBUF)
SCK_IN: R26.1 U11.1 U22.83(IO7) X14.1
SCK_IN2: J4.4(SCK/SCL) R32.1 U11.2
SCKI+/SDO1: R11.1 R48.1 R51.1 R53.1 X4.1
SCKI-/SCKI: R13.1 R32.2 R47.1 R51.2 R53.2 X6.1
SCKO+/SCKO: R12.1 R54.1 U22.50(IO8_DIFFIOB9N) X5.1
SCKO-/SDO2: R15.1 R54.2 U22.49(IO7_DIFFIOB9P) X8.1
SCL: J4.11(EESCL) P1.87 R92.1 U8.2(SCL) U24.6(SCL)
SDA: J4.9(EESDA) P1.91 R93.1 U8.4(SDA) U24.5(SDA)
SDI+: R56.1 R57.1 R58.1 U1.16(SDI+) X2.1
SDI-/SDO0: J4.5(MISO) R16.1 R55.1 R56.2 R57.2 X9.1
SDI_IN: R25.1 U10.1 U22.84(IO8_DIFFIOR8N) X13.1
SDO+/SDO3: R14.1 R50.1 U22.39(IO2_DIFFIOB1N) X7.1
SDO-/SDI: J4.7(MOSI/SDA) R10.1 R50.2 U10.2 U22.38(IO1_DIFFIOB1P) X3.1
SS0: P1.98 R63.1
SS1: P1.94 R64.1
SS2: P1.92 R66.1
SYNC: P1.52 R80.1
TCK: J3.1 R104.1 U22.16(TCK)
TDI: J3.9 R98.2 U22.15(TDI)
TDO: J3.3 U22.20(TDO)
TMS: J3.5 R99.2 U22.18(TMS)
VCM: R115.1 R117.1 R124.1 R125.1 R128.1 R138.1 R176.1 U33.1(OUT)
WRIN: R9.1 R23.2 R24.1 U22.85(IO9_DIFFIOR8P) X12.1
WRIN2: R23.1 R29.1 U13.2 U22.3(IO3) X17.1
WRIN2L: R33.1 U9.4 U10.4 U11.4 U12.4 X20.1
N928027: C3.2 R1.2 R5.1 U2.2
N928109: C3.1 J1.1 R4.1
N928437: R2.2 U3.2 U4.1(CP)
N929285: R6.1 U4.7(~{PR})
N940093: C34.2 U17.4(BYP)
N940147: JP2.2 R40.2 R41.1 U17.2(SEN)
N979025: R3.1 U3.4
N1083481: R6.2 U5.4
N4148550: C37.2 U18.4(BYP)
N4148570: R43.2 R44.1 U18.2(SEN)
N5992639: R21.1 U1.13(PD)
N5993083: R22.1 U1.27(CSL)
N6131415: C15.2 JP1.2 U1.10(REFIN)
N7164409: C100.1 R107.2 R110.2 U25.5(IN+)
N7164437: C112.1 R109.2 R124.2 U25.3(IN+)
N7164481: R113.2 U25.6(IN-)
N9606066: R10.2 U1.25(SDO-/SDI)
N9606989: R11.2 U1.18(SCKI+/SDO1)
N9609820: R12.2 U1.22(SCKO+/SCKO)
N9609836: R13.2 U1.19(SCKI-/SCKI)
N9610867: R14.2 U1.24(SDO+/SDO3)
N9610883: R15.2 U1.23(SCKO-/SDO2)
N9611920: R16.2 U1.17(SDI-/SDO0)
N9611936: R17.2 U1.26(BUSY)
N9659090: R9.2 U6.4
N10801258: C42.2 U20.4(BYP)
N10809399: R45.2 R46.1 U21.2(SEN)
N10809527: C45.2 U21.4(BYP)
N10819774: R38.2 R39.1 U16.2(SEN)
N10819902: C31.2 U16.4(BYP)
N10825550: R34.2 R36.1 U14.4(ADJ)
N10881449: J2.3 R100.2 U22.92(CONF_DONE)
N10881623: R95.2 U22.98(IO6_INIT_DONE)
N10881677: C81.2 D3.2 J2.8 U22.8(IO2_FLASH_NCE) U23.1(NCS)
N10881707: R84.2 U22.124(IO10)
N10881711: R86.2 U22.125(IO11)
N10881735: R90.2 U22.127(IO13_DIFFIOT12P)
N10882057: C79.2 D1.2 J2.7 U22.13(IO3_DATA0) U23.2(DATA)
N10882603: C80.2 D2.2 J2.1 U22.12(DCLK) U23.6(DCLK)
N10883255: C82.2 D4.2 J2.9 U22.6(IO1_DATA1) U23.5(ASDI)
N10884549: R88.2 U22.126(IO12_DIFFIOT12N)
N10885053: J2.5 R97.2 U22.14(NCONFIG)
N10885699: R101.1 U22.87(IO5_DEV_CLRN)
N10885829: R96.2 U22.9(N_STATUS)
N10885885: R102.1 U22.86(IO4_DEV_OE)
N10891445: C47.2 J4.10(EEVCC) P1.93 R92.2 R93.2 R94.2 U24.8(VCC)
N10891855: JP4.2 R94.1 U24.7(WP)
N10892093: P1.97 R91.2
N10997996: JP3.2 U22.33(IO5_RDN1)
N11046555: R47.2 U22.59(IO4_DIFFIOB16P)
N11065782: R48.2 U22.60(IO5_DIFFIOB16N)
N11089379: R55.2 U22.70(IO12_DIFFIOB21P)
N11090651: R58.2 U22.71(IO13_DIFFIOB21N)
N11127617: R65.2 U22.77(IO4_RDN3)
N11127621: R67.2 U22.79(IO5)
N11197847: R68.2 U22.106(IO4)
N11197851: R66.2 U22.105(IO3_VREF6)
N11198954: R64.2 U22.104(IO2)
N11198958: R63.2 U22.100(IO1)
N11221301: R76.2 U22.115(IO6_RDN4)
N11221305: R78.2 U22.119(IO7_VREF7)
N11221309: R82.2 U22.121(IO9_DIFFIOT16P)
N11221337: R80.2 U22.120(IO8_DIFFIOT16N)
N11222408: R74.2 U22.114(IO5_RUP4)
N11224534: R70.2 U22.111(IO2)
N11224560: R62.2 U22.110(IO1)
N11274502: R71.2 U22.129(IO2_DIFFIOT11P)
N11274528: R69.2 U22.128(IO1_DIFFIOT11N)
N11279563: R73.2 U22.133(IO4_DIFFIOT10P)
N11279587: R72.2 U22.132(IO3_DIFFIOT10N)
N11280655: R77.2 U22.136(IO6_VREF8)
N11280679: R75.2 U22.135(IO5)
N11281755: R81.2 U22.138(IO8)
N11281779: R79.2 U22.137(IO7)
N11282863: R85.2 U22.142(IO10)
N11282887: R83.2 U22.141(IO9)
N11283979: R89.2 U22.144(IO12_DIFFIOT01P)
N11284003: R87.2 U22.143(IO11_DIFFIOT01N)
N11317172: R24.2 U8.20(P7)
N11317192: R25.2 U8.19(P6)
N11317212: R26.2 U8.17(P5)
N11317272: R27.2 U8.16(P4)
N11317308: R28.2 U8.14(P3)
N11317424: R29.2 U8.12(P2)
N11317448: R30.2 U8.11(P1)
N11317468: R31.2 U8.10(P0)
N11684985: R33.2 U13.4
N12089373: R59.2 R61.2 U22.75(IO3)
N12776393: R8.1 U6.1
N12850146: R2.1 U2.4
N15670275: JP2.3 R42.1
N15702031: C116.2 R123.1 R129.2 U25.1(OUT)
N15702135: C116.1 R119.1 R129.1 U25.2(IN-)
N17136265: R108.1 R113.1 R119.2 U25.7(OUT)
N17163895: C26.1 J7.1 J7.2 J7.3 J7.4 JP14.1 R117.2 R118.2
N17169658: C26.2 J6.1 JP14.2
N17170951: C25.1 J7.9 J7.10 J7.11 J7.12 JP13.1 R115.2 R116.2
N18367471: R112.1 R114.1 R120.2 U26.7(OUT)
N18367477: C117.1 R120.1 R130.1 U26.2(IN-)
N18367487: C117.2 R126.1 R130.2 U26.1(OUT)
N18367531: C113.1 R110.1 R125.2 U26.3(IN+)
N18367582: C101.1 R109.1 R111.2 U26.5(IN+)
N18367630: R114.2 U26.6(IN-)
N18391255: C25.2 J5.1 JP13.2
N18597492: C125.2 R131.2 R132.1 U28.1(OUT)
N18597518: C108.1 R122.2 R137.1 U28.5(IN+)
N18597522: R121.1 R127.1 R142.2 U28.7(OUT)
N18597556: C114.1 R128.2 R139.1 U28.3(IN+)
N18597558: R127.2 U28.6(IN-)
N18597684: R133.2 R135.1 R136.1 U27.7(OUT)
N18597692: C118.1 R133.1 R140.1 U27.2(IN-)
N18597702: C118.2 R140.2 R141.1 U27.1(OUT)
N18597746: C121.1 R137.2 R138.2 U27.3(IN+)
N18597803: C120.1 R134.2 R139.2 U27.5(IN+)
N18597847: R136.2 U27.6(IN-)
N18597990: C125.1 R131.1 R142.1 U28.2(IN-)
N18668999: C29.1 JP15.1 JP15.3 JP15.5 JP15.7 U33.3(IN+)
N18678687: R176.2 U33.4(IN-)
N18713307: C160.1 E13.1(A) JP15.2
N18727683: JP15.4 R175.1 R177.2
N18729384: JP15.6 R177.1 R178.2
N19360315: R8.2 U4.3(~{Q})

Not connected (* = marked no-connect by the designer): J3 7* 8*; J4 1(V+)* 2(5V)* 14(AUX)*; JP1 1*; JP2 1*; JP4 1*; JP13 3*; JP14 3*; P1 62* 64* 68* 70* 74* 80* 99* 100*; U4 5(Q)*; U8 1(INTL)* 3(NC)* 8(NC)* 13(NC)* 18(NC)*; U22 7(IO5_VREF1)* 10(IO6_DIFFL4P)* 11(IO7_DIFFL4N)* 22(CLK0)* 23(CLK1)* 24(CLK2)* 30(IO2)* 31(IO3_VREF2)* 32(IO4_RUP1)* 34(IO6)* 42(IO3)* 43(IO4)* 44(IO5)* 46(IO6_VREF3)* 51(IO9)* 52(IO10_DIFFIOB11P)* 53(IO11_DIFFIOB11N)* 54(IO1_DIFFIOB12P)* 55(IO2_DIFFIOB12N)* 58(IO3)* 64(IO6)* 65(IO7_VREF4)* 66(IO8_RUP2)* 67(IO9_RDN2)* 68(IO10)* 69(IO11)* 72(IO14)* 74(IO2)* 76(IO4_RUP3)* 88(CLK7_DIFFCLK3N)* 89(CLK6_DIFFCLK3P)* 90(CLK5_DIFFCLK2N)* 91(CLK4_DIFFCLK2P)* 99(IO7_CRC_ERROR)* 101(IO8_NCEO)* 112(IO3)* 113(IO4)*; U25 EP*; U26 EP*; U27 EP*; U28 EP*

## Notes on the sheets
sheet 1
- CLK
- 100MHz MAX
- 2.5VPP
- 0402 X 8PLCS
- NOTES: UNLESS OTHERWISE SPECIFIED
- *
- ASSY
- U1
- SUFFIX
- -Bit
- Ksps
- R61
- 1.  ALL RESISTORS AND CAPACITORS ON THIS PAGE ARE 0603.
- A
- LTC2344-18
- 18
- 18
- 400
- 0
- B
- LTC2344-16
- 16
- 16
- 400
- OPT
sheet 2
- VEE
- +9V / +10V
- VCC
- -9V / -10V
- GND
- VCCIO
- VDD
- +1.2V
- VCCINT
- +2.5V
- +3V
- NOTES: UNLESS OTHERWISE SPECIFIED
- 1.  ALL RESISTORS AND CAPACITORS ON THIS PAGE ARE 0603.
sheet 3
- FPGA
- PROGRAM
- DC590/DC2026
- JTAG
- NOTES: UNLESS OTHERWISE SPECIFIED
- 1.  ALL RESISTORS AND CAPACITORS ON THIS PAGE ARE 0402.
- 2.  R61 IS O OHMS ON "A" ASSEMBLY TYPE AND OPTIONAL ON "B" ASSEMBLY TYPE.
- (A)
sheet 4
- VIN1
- 0V - 5V
- AIN0
- AIN2
- AIN0
- AIN1
- AIN2
- AIN3
- VIN2
- VIN1
- VIN2
- 0V - 5V
- AIN1
- AIN3
- EXT
- 2.048V
- 2.5V
- GND
- NOTES: UNLESS OTHERWISE SPECIFIED
- 1.  ALL RESISTORS AND CAPACITORS ON THIS PAGE ARE 0402.
